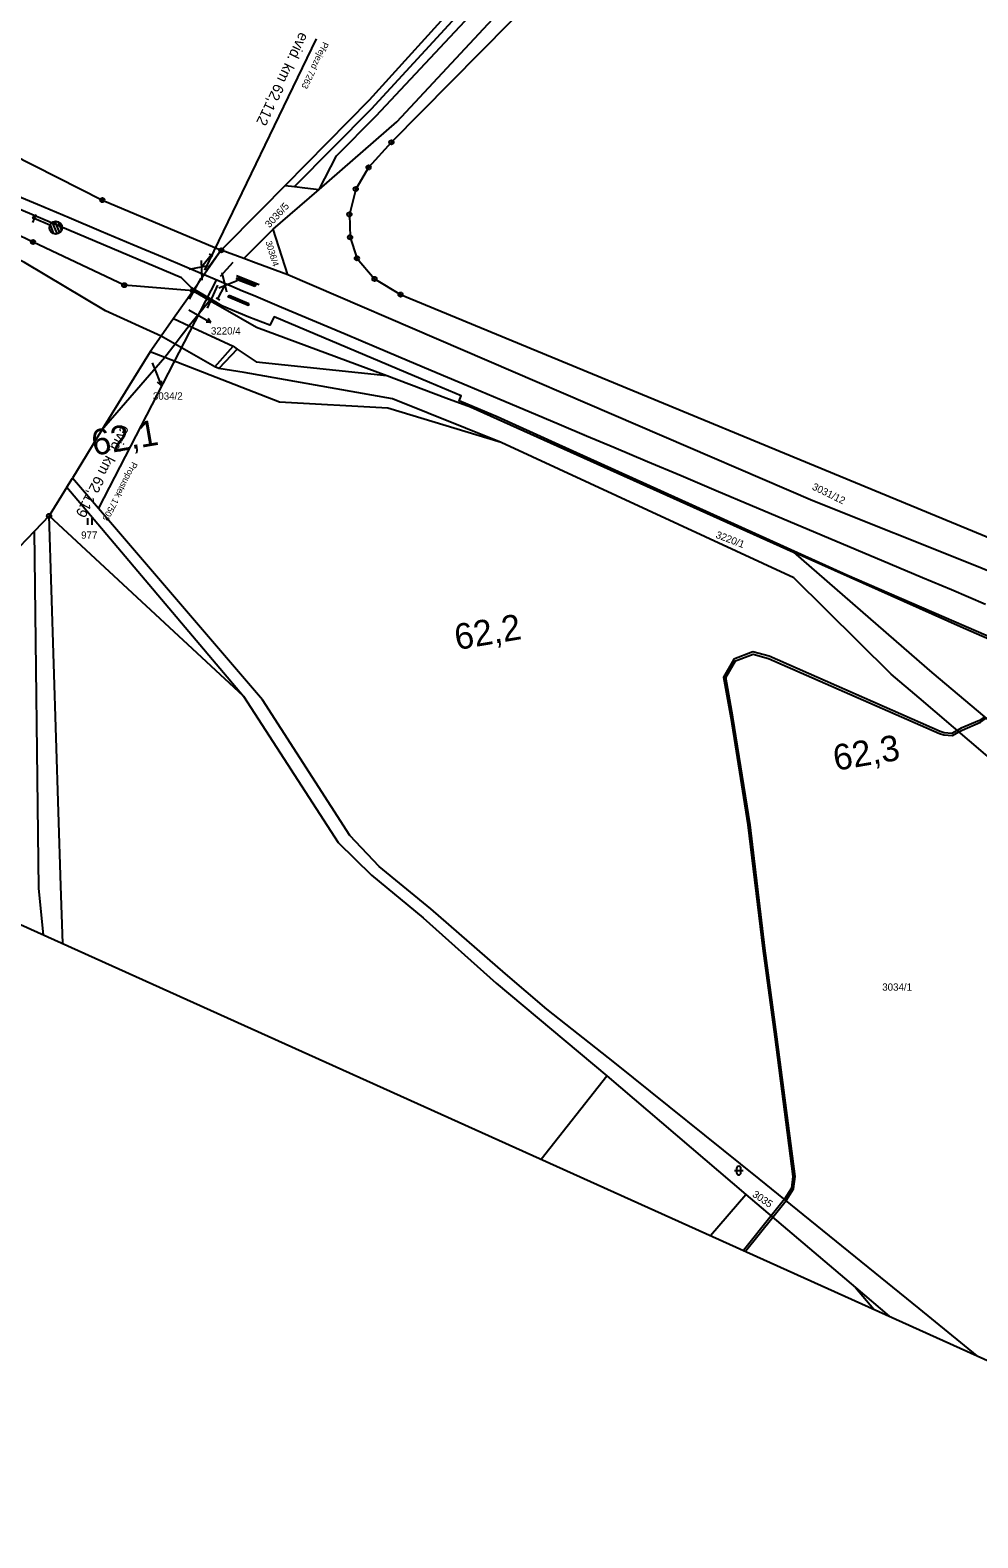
# Model space of a CAD drawing. Extents: x -621716 to -621020, y -1122350 to -1121821.
# Drawn here: x -621457.9 to -621236.3, y -1122350.4 to -1121998 of the extents above; entities that cross this region are included whole.
import ezdxf

# ---------------------------------------------------------------- set-up
doc = ezdxf.new("R2010")
doc.units = 0
for name, color, linetype in [('hm', 7, 'Continuous'), ('HranDP', 7, 'Continuous'), ('Hranice parcel', 7, 'Continuous'), ('Parcelní čísla', 7, 'Continuous'), ('Pop  PČ popisy', 7, 'Continuous'), ('Rámečky-tisk', 7, 'Continuous'), ('STANICENI NOVE HM', 7, 'Continuous'), ('Vnitřní kresba', 7, 'Continuous'), ('Vrstva 1', 7, 'Continuous'), ('Vrstva 18', 7, 'Continuous'), ('Vrstva 19', 7, 'Continuous'), ('Vrstva 2', 7, 'Continuous'), ('Vrstva 4', 7, 'Continuous'), ('Vrstva 51', 7, 'Continuous'), ('Věcná břemena k části', 7, 'Continuous'), ('Značky bodu BP', 7, 'Continuous'), ('Značky kultur', 7, 'Continuous')]:
    doc.layers.add(name, color=color, linetype=linetype)

msp = doc.modelspace()

# ---------------------------------------------------------------- linework, layer by layer
at = {"layer": 'hm'}
for p, q in [((-621420.45, -1122053.43), (-621420.45, -1122053.43)), ((-621328.28, -1122092.36), (-621328.28, -1122092.36))]:
    msp.add_line(p, q, dxfattribs=at)
at = {"layer": 'HranDP'}
for p, q in [((-621407.88, -1122051.37), (-621413.16, -1122049.43)), ((-621419.76, -1122058.87), (-621415.82, -1122061.13)), ((-621240.3, -1122137.45), (-621279.41, -1122120.03))]:
    msp.add_line(p, q, dxfattribs=at)
for points in [[(-621652.52, -1121949.92), (-621634.32, -1121957.84), (-621586.09, -1121979.87), (-621558.65, -1121986.81), (-621503.12, -1122006.48), (-621467.56, -1122024.2), (-621440.98, -1122037.68), (-621413.16, -1122049.43)], [(-621419.76, -1122058.87), (-621435.87, -1122057.58), (-621457.19, -1122047.49), (-621484.84, -1122034.47), (-621524.13, -1122018.29), (-621524.58, -1122018.11), (-621531.16, -1122015.54)], [(-621397.6, -1122055.13), (-621405.03, -1122052.42), (-621407.88, -1122051.37)], [(-621236.6, -1122123.3), (-621274.82, -1122107.97), (-621397.6, -1122055.13)], [(-621415.82, -1122061.13), (-621412.83, -1122062.84), (-621404.9, -1122067.41), (-621374.43, -1122078.72), (-621360.65, -1122083.94), (-621354.93, -1122086.03), (-621279.41, -1122120.03)], [(-621071.57, -1122194.18), (-621089.46, -1122186.34), (-621091.58, -1122185.41), (-621183.06, -1122145.34), (-621236.6, -1122123.3)], [(-621077.02, -1122206.26), (-621096.79, -1122198.16), (-621171.69, -1122167.46), (-621240.3, -1122137.45)]]:
    msp.add_lwpolyline(points, dxfattribs=at)
at = {"layer": 'Hranice parcel'}
for p, q in [((-621338.16, -1121969.67), (-621378.6, -1122014.36)), ((-621338.16, -1121969.67), (-621378.6, -1122014.36)), ((-621378.6, -1122014.36), (-621398.24, -1122034.29)), ((-621378.6, -1122014.36), (-621398.24, -1122034.29)), ((-621390.3, -1122035.18), (-621372.11, -1122019.37)), ((-621398.24, -1122034.29), (-621403.84, -1122039.98)), ((-621398.24, -1122034.29), (-621403.84, -1122039.98)), ((-621398.24, -1122034.29), (-621396.07, -1122034.53)), ((-621403.84, -1122039.98), (-621413.16, -1122049.43)), ((-621403.84, -1122039.98), (-621413.16, -1122049.43)), ((-621401.06, -1122044.51), (-621407.88, -1122051.37)), ((-621397.6, -1122055.13), (-621401.06, -1122044.51)), ((-621413.16, -1122049.43), (-621417.06, -1122055.01)), ((-621413.16, -1122049.43), (-621417.06, -1122055.01)), ((-621407.88, -1122051.37), (-621413.16, -1122049.43)), ((-621417.06, -1122055.01), (-621419.76, -1122058.87)), ((-621417.06, -1122055.01), (-621419.76, -1122058.87)), ((-621419.76, -1122058.87), (-621424.34, -1122065.38)), ((-621419.76, -1122058.87), (-621424.34, -1122065.38)), ((-621419.76, -1122058.87), (-621415.82, -1122061.13)), ((-621424.34, -1122065.38), (-621427.21, -1122069.47)), ((-621424.34, -1122065.38), (-621427.21, -1122069.47)), ((-621427.21, -1122069.47), (-621429.78, -1122073.13)), ((-621427.21, -1122069.47), (-621429.78, -1122073.13)), ((-621423.93, -1122071.34), (-621427.21, -1122069.47)), ((-621414.64, -1122076.64), (-621423.93, -1122071.34)), ((-621441.14, -1122091.59), (-621447.98, -1122102.71)), ((-621441.14, -1122091.59), (-621447.98, -1122102.71)), ((-621449.3, -1122104.83), (-621447.98, -1122102.71)), ((-621449.3, -1122104.83), (-621447.98, -1122102.71)), ((-621449.3, -1122104.83), (-621453.42, -1122111.52)), ((-621449.3, -1122104.83), (-621453.42, -1122111.52)), ((-621449.3, -1122104.83), (-621407.95, -1122153.65)), ((-621449.3, -1122104.83), (-621407.95, -1122153.65)), ((-621453.42, -1122111.52), (-621456.82, -1122115.07)), ((-621453.42, -1122111.52), (-621456.82, -1122115.07)), ((-621407.95, -1122153.65), (-621453.42, -1122111.52)), ((-621456.82, -1122115.07), (-621487.9, -1122147.44)), ((-621456.82, -1122115.07), (-621487.9, -1122147.44)), ((-621240.3, -1122137.45), (-621279.41, -1122120.03)), ((-621407.95, -1122153.65), (-621385.83, -1122187.85)), ((-621407.95, -1122153.65), (-621385.83, -1122187.85)), ((-621348.86, -1122220.77), (-621323.04, -1122242.46)), ((-621348.86, -1122220.77), (-621323.04, -1122242.46)), ((-621323.04, -1122242.46), (-621290.49, -1122270.16)), ((-621323.04, -1122242.46), (-621290.49, -1122270.16)), ((-621290.49, -1122270.16), (-621264.88, -1122291.93)), ((-621290.49, -1122270.16), (-621264.88, -1122291.93)), ((-621264.88, -1122291.93), (-621257.02, -1122298.61)), ((-621264.88, -1122291.93), (-621257.02, -1122298.61))]:
    msp.add_line(p, q, dxfattribs=at)
for points in [[(-621652.52, -1121949.92), (-621634.32, -1121957.84), (-621586.09, -1121979.87), (-621558.65, -1121986.81), (-621503.12, -1122006.48), (-621467.56, -1122024.2), (-621440.98, -1122037.68), (-621413.16, -1122049.43)], [(-621390.3, -1122035.18), (-621386.25, -1122027.37), (-621376.94, -1122017.95), (-621351.6, -1121990.87), (-621337.62, -1121976.15), (-621310.12, -1121948.89)], [(-621316.28, -1121963.73), (-621318.05, -1121968.15), (-621373.38, -1122024.18), (-621378.72, -1122030.05), (-621381.72, -1122035.12), (-621383.2, -1122041.04), (-621383.06, -1122046.37), (-621381.45, -1122051.28), (-621377.34, -1122056.11), (-621371.25, -1122059.79), (-621220, -1122122.28), (-621154.89, -1122148.82), (-621067.38, -1122184.88)], [(-621396.07, -1122034.53), (-621378.06, -1122016.33), (-621337.5, -1121972.28)], [(-621372.11, -1122019.37), (-621337.97, -1121982.66), (-621329.83, -1121972.98)], [(-621419.76, -1122058.87), (-621435.87, -1122057.58), (-621457.19, -1122047.49), (-621484.84, -1122034.47), (-621524.13, -1122018.29), (-621524.58, -1122018.11), (-621531.16, -1122015.54)], [(-621427.21, -1122069.47), (-621440.23, -1122063.56), (-621459.21, -1122052.3), (-621481.49, -1122041.55), (-621489.69, -1122037.91), (-621514.45, -1122027.88), (-621531.58, -1122025.1), (-621539.57, -1122026.3)], [(-621401.06, -1122044.51), (-621397.09, -1122041.07), (-621390.3, -1122035.18)], [(-621396.07, -1122034.53), (-621393.61, -1122034.81), (-621390.3, -1122035.18)], [(-621397.6, -1122055.13), (-621405.03, -1122052.42), (-621407.88, -1122051.37)], [(-621236.6, -1122123.3), (-621274.82, -1122107.97), (-621397.6, -1122055.13)], [(-621415.82, -1122061.13), (-621420.66, -1122067.08), (-621422.55, -1122069.54), (-621423.93, -1122071.34)], [(-621415.82, -1122061.13), (-621412.83, -1122062.84), (-621404.9, -1122067.41), (-621374.43, -1122078.72), (-621360.65, -1122083.94), (-621354.93, -1122086.03), (-621279.41, -1122120.03)], [(-621423.93, -1122071.34), (-621426.34, -1122074.48), (-621441.14, -1122091.59)], [(-621429.78, -1122073.13), (-621435, -1122081.61), (-621441.14, -1122091.59)], [(-621429.78, -1122073.13), (-621435, -1122081.61), (-621441.14, -1122091.59)], [(-621187.4, -1122207.5), (-621250, -1122154.05), (-621256.5, -1122148.5), (-621279.33, -1122126.02), (-621347.74, -1122094.36), (-621373.17, -1122084.12), (-621407.84, -1122078), (-621413.72, -1122077.04), (-621414.64, -1122076.64)], [(-621236.42, -1122307.9), (-621250, -1122296.86), (-621287.36, -1122266.52), (-621321.13, -1122239.4), (-621337.07, -1122226.87), (-621346.7, -1122218.55), (-621364.2, -1122203.4), (-621376.27, -1122193.53), (-621383.11, -1122186.25), (-621403.55, -1122154.5), (-621447.98, -1122102.71)], [(-621450.22, -1122211.51), (-621450.7, -1122198.05), (-621453.42, -1122111.52)], [(-621454.75, -1122209.47), (-621455.81, -1122198.63), (-621456.82, -1122115.07)], [(-621279.41, -1122120.03), (-621250, -1122145.55), (-621247, -1122148.15)], [(-621071.57, -1122194.18), (-621089.46, -1122186.34), (-621091.58, -1122185.41), (-621183.06, -1122145.34), (-621236.6, -1122123.3)], [(-621077.02, -1122206.26), (-621096.79, -1122198.16), (-621171.69, -1122167.46), (-621240.3, -1122137.45)], [(-621247, -1122148.15), (-621183.91, -1122201.29), (-621138.49, -1122229.74), (-621120.6, -1122238.74), (-621097.01, -1122250.61)], [(-621385.83, -1122187.85), (-621378.02, -1122195.51), (-621365.96, -1122205.51), (-621348.86, -1122220.77)], [(-621385.83, -1122187.85), (-621378.02, -1122195.51), (-621365.96, -1122205.51), (-621348.86, -1122220.77)], [(-621338.34, -1122261.95), (-621323.04, -1122242.46)], [(-621298.77, -1122279.79), (-621290.49, -1122270.16)], [(-621264.88, -1122291.93), (-621260.6, -1122296.99)]]:
    msp.add_lwpolyline(points, dxfattribs=at)
at = {"layer": 'Pop  PČ popisy'}
for p, q in [((-621420.74, -1122063.35), (-621418.19, -1122064.8)), ((-621418.19, -1122064.8), (-621415.59, -1122066.3)), ((-621415.59, -1122066.3), (-621416.71, -1122066.23)), ((-621415.59, -1122066.3), (-621416.21, -1122065.37)), ((-621429.33, -1122075.75), (-621428.34, -1122078.24)), ((-621428.34, -1122078.24), (-621427.22, -1122081.02)), ((-621427.22, -1122081.02), (-621428.06, -1122080.28)), ((-621427.22, -1122081.02), (-621427.13, -1122079.91))]:
    msp.add_line(p, q, dxfattribs=at)
at = {"layer": 'Rámečky-tisk'}
msp.add_lwpolyline([(-621594.3, -1121820.78), (-621716.36, -1122091.54), (-621142.02, -1122350.45)], dxfattribs=at)
at = {"layer": 'Vnitřní kresba'}
for p, q in [((-621409.58, -1122056.22), (-621409.4, -1122055.76)), ((-621405.31, -1122057.91), (-621409.58, -1122056.22)), ((-621409.4, -1122055.76), (-621405.12, -1122057.45)), ((-621411.51, -1122060.4), (-621411.33, -1122059.94)), ((-621406.92, -1122062.32), (-621411.51, -1122060.4)), ((-621411.33, -1122059.94), (-621406.73, -1122061.86)), ((-621405.12, -1122057.45), (-621405.31, -1122057.91)), ((-621406.73, -1122061.86), (-621406.92, -1122062.32)), ((-621424.34, -1122065.38), (-621420.66, -1122067.08)), ((-621420.66, -1122067.08), (-621410.38, -1122071.81)), ((-621426.34, -1122074.48), (-621429.78, -1122073.13)), ((-621399.58, -1122084.94), (-621426.34, -1122074.48)), ((-621414.64, -1122076.64), (-621410.38, -1122071.81)), ((-621409.44, -1122072.55), (-621413.72, -1122077.04)), ((-621410.38, -1122071.81), (-621409.44, -1122072.55)), ((-621409.44, -1122072.55), (-621405.01, -1122075.53)), ((-621405.01, -1122075.53), (-621374.43, -1122078.72)), ((-621374.22, -1122086.34), (-621399.58, -1122084.94)), ((-621347.74, -1122094.36), (-621374.22, -1122086.34))]:
    msp.add_line(p, q, dxfattribs=at)
at = {"layer": 'Vrstva 1'}
for p, q in [((-621456.94, -1122041.27), (-621465.24, -1122037.77)), ((-621414.87, -1122061.31), (-621420.14, -1122058.23)), ((-621413.03, -1122062.38), (-621414.87, -1122061.31)), ((-621406.73, -1122065.04), (-621413.03, -1122062.38))]:
    msp.add_line(p, q, dxfattribs=at)
for points in [[(-621463.6, -1122035.5), (-621456.14, -1122038.65), (-621448.71, -1122041.78), (-621441.28, -1122044.92), (-621433.82, -1122048.06), (-621426.01, -1122051.35), (-621418.67, -1122054.45), (-621413.13, -1122056.78), (-621410.7, -1122057.8), (-621408.17, -1122058.87), (-621405.64, -1122059.94), (-621399.12, -1122062.69), (-621391.8, -1122065.77), (-621384.21, -1122068.97), (-621376.84, -1122072.09), (-621369.7, -1122075.09), (-621362.7, -1122078.04), (-621355.46, -1122081.1), (-621348.02, -1122084.24), (-621341.21, -1122087.11), (-621334.15, -1122090.09), (-621327.75, -1122092.8), (-621321.37, -1122095.49), (-621313.5, -1122098.8), (-621305.66, -1122102.11), (-621297.43, -1122105.59), (-621288.95, -1122109.16), (-621280.64, -1122112.66), (-621272.65, -1122116.04), (-621264.7, -1122119.38), (-621256.74, -1122122.74), (-621249.24, -1122125.9), (-621242.46, -1122128.76), (-621234.48, -1122132.13)], [(-621456.93, -1122042.01), (-621457.21, -1122041.89), (-621456.94, -1122041.27)], [(-621420.14, -1122058.23), (-621422.44, -1122055.84), (-621456.94, -1122041.27)], [(-621085.52, -1122202.49), (-621145.97, -1122177.73), (-621266.9, -1122125.34), (-621335.07, -1122094.53), (-621348.64, -1122088.4), (-621357.58, -1122084.62), (-621357.08, -1122083.45), (-621364.5, -1122080.32), (-621400.77, -1122065), (-621401.81, -1122066.92), (-621406.73, -1122065.04)]]:
    msp.add_lwpolyline(points, dxfattribs=at)
at = {"layer": 'Vrstva 18'}
for p, q in [((-621404.34, -1122057.53), (-621409.61, -1122055.39)), ((-621406.64, -1122062.36), (-621411.73, -1122060.23))]:
    msp.add_line(p, q, dxfattribs=at)
at = {"layer": 'Vrstva 19'}
msp.add_line((-621441.76, -1122109.75), (-621414.31, -1122056.4), dxfattribs=at)
at = {"layer": 'Vrstva 2'}
for p, q in [((-621456.54, -1122041.09), (-621457.32, -1122042.93)), ((-621453.25, -1122043.57), (-621456.93, -1122042.01)), ((-621452.68, -1122042.89), (-621451.57, -1122045.62)), ((-621452.05, -1122042.66), (-621450.99, -1122045.37)), ((-621451.37, -1122042.73), (-621450.52, -1122044.82)), ((-621453.21, -1122043.48), (-621452.36, -1122045.57))]:
    msp.add_line(p, q, dxfattribs=at)
msp.add_circle((-621451.86, -1122044.15), 1.5, dxfattribs=at)
at = {"layer": 'Vrstva 4'}
for p, q in [((-621417.03, -1122054.04), (-621390.9, -1122000.02)), ((-621416.24, -1122053.04), (-621420.78, -1122053.89)), ((-621417.66, -1122056.39), (-621417.8, -1122051.78)), ((-621415.55, -1122050.58), (-621417.74, -1122053.31)), ((-621415.16, -1122050.89), (-621415.94, -1122050.26)), ((-621418.67, -1122054.45), (-621413.13, -1122056.78)), ((-621413.76, -1122058.2), (-621409.49, -1122056.47)), ((-621413.04, -1122054.64), (-621411.98, -1122059.12)), ((-621414.4, -1122060.52), (-621413.51, -1122060.98)), ((-621413.95, -1122060.75), (-621412.34, -1122057.64))]:
    msp.add_line(p, q, dxfattribs=at)
at = {"layer": 'Vrstva 51'}
for p, q in [((-621413.66, -1122050.02), (-621416.66, -1122054.16)), ((-621410.46, -1122052.3), (-621413.39, -1122055.56)), ((-621420.6, -1122060.83), (-621417.9, -1122055.93)), ((-621416.39, -1122062.99), (-621413.99, -1122057.55))]:
    msp.add_line(p, q, dxfattribs=at)
at = {"layer": 'Věcná břemena k části'}
msp.add_line((-621291.09, -1122283.25), (-621290.63, -1122283.46), dxfattribs=at)
for points in [[(-621242.32, -1122162.36), (-621244.11, -1122162.22), (-621245.08, -1122161.9), (-621285.04, -1122144.35), (-621288.86, -1122143.32), (-621293.29, -1122145), (-621295.74, -1122149.19), (-621294.06, -1122158.66), (-621290.04, -1122183.78), (-621286.56, -1122212.67), (-621283.77, -1122233.35), (-621279.5, -1122265.97), (-621279.82, -1122268.68), (-621281.5, -1122271.28), (-621281.11, -1122271.59), (-621281.1, -1122271.58), (-621279.34, -1122268.86), (-621279, -1122265.97), (-621283.27, -1122233.29), (-621286.06, -1122212.61), (-621289.54, -1122183.72), (-621293.56, -1122158.58), (-621295.22, -1122149.29), (-621292.95, -1122145.4), (-621288.84, -1122143.84), (-621285.2, -1122144.83), (-621245.26, -1122162.36), (-621244.21, -1122162.72), (-621242.2, -1122162.86), (-621240.68, -1122162.01), (-621241.08, -1122161.66)], [(-621234.35, -1122158.81), (-621234.74, -1122158.48), (-621235.87, -1122159.33), (-621240.17, -1122161.16), (-621241.08, -1122161.66), (-621240.68, -1122162.01), (-621239.95, -1122161.6), (-621235.61, -1122159.77)], [(-621281.11, -1122271.59), (-621281.5, -1122271.28), (-621284.61, -1122275.16), (-621284.23, -1122275.48)]]:
    msp.add_lwpolyline(points, close=True, dxfattribs=at)
msp.add_lwpolyline([(-621290.63, -1122283.46), (-621284.23, -1122275.48), (-621284.61, -1122275.16), (-621291.09, -1122283.25)], dxfattribs=at)
at = {"layer": 'Značky bodu BP'}
for centre, radius in [((-621373.38, -1122024.18), 0.5), ((-621373.38, -1122024.18), 0.0303), ((-621378.72, -1122030.05), 0.5), ((-621378.72, -1122030.05), 0.0303), ((-621381.72, -1122035.12), 0.5), ((-621381.72, -1122035.12), 0.0303), ((-621440.98, -1122037.68), 0.5), ((-621440.98, -1122037.68), 0.0303), ((-621383.2, -1122041.04), 0.5), ((-621383.2, -1122041.04), 0.0303), ((-621383.06, -1122046.37), 0.5), ((-621383.06, -1122046.37), 0.0303), ((-621457.19, -1122047.49), 0.5), ((-621457.19, -1122047.49), 0.0303), ((-621413.16, -1122049.43), 0.5), ((-621413.16, -1122049.43), 0.0303), ((-621381.45, -1122051.28), 0.5), ((-621381.45, -1122051.28), 0.0303), ((-621435.87, -1122057.58), 0.5), ((-621377.34, -1122056.11), 0.5), ((-621377.34, -1122056.11), 0.0303), ((-621435.87, -1122057.58), 0.0303), ((-621419.76, -1122058.87), 0.5), ((-621419.76, -1122058.87), 0.0303), ((-621371.25, -1122059.79), 0.5), ((-621371.25, -1122059.79), 0.0303), ((-621453.42, -1122111.52), 0.5), ((-621453.42, -1122111.52), 0.0303)]:
    msp.add_circle(centre, radius, dxfattribs=at)
at = {"layer": 'Značky kultur'}
for p, q in [((-621444.37, -1122113.59), (-621444.37, -1122112.09)), ((-621443.37, -1122113.59), (-621443.37, -1122112.09)), ((-621293.17, -1122264.59), (-621291.17, -1122264.59)), ((-621292.67, -1122264.09), (-621292.67, -1122265.09)), ((-621291.67, -1122265.09), (-621291.67, -1122264.09))]:
    msp.add_line(p, q, dxfattribs=at)
for centre, start, end in [((-621292.17, -1122264.09), 0, 180), ((-621292.17, -1122265.09), 180, 359.9879)]:
    msp.add_arc(centre, 0.5, start, end, dxfattribs=at)

# ---------------------------------------------------------------- texts
at = {"layer": 'Parcelní čísla'}
for s, height, rotation, p in [('3036/5', 1.7, 47, (-621401.9, -1122044.31)), ('3036/4', 1.5, 287, (-621402.85, -1122047.46)), ('3031/12', 1.7, 334, (-621275.18, -1122105.26)), ('3220/1', 1.7, 339, (-621297.7, -1122116.58)), ('3035', 1.7, 326, (-621289.15, -1122270.52))]:
    msp.add_text(s, height=height, rotation=rotation, dxfattribs=at).set_placement(p)
for s, p in [('3220/4', (-621415.59, -1122069.12)), ('3034/2', (-621429.15, -1122084.35)), ('977', (-621445.93, -1122116.86)), ('3034/1', (-621258.62, -1122222.53))]:
    msp.add_text(s, height=1.7, dxfattribs=at).set_placement(p)
at = {"layer": 'STANICENI NOVE HM'}
for s, p in [('62,1', (-621442.96, -1122097.48)), ('62,2', (-621358.1, -1122142.91)), ('62,3', (-621269.56, -1122171.14))]:
    msp.add_text(s, height=6, rotation=9.6991, dxfattribs=at).set_placement(p)
at = {"layer": 'Vrstva 19'}
for s, height, p in [('evid. km 62,119', 2.5, (-621436.41, -1122090.12)), ('Propustek 17503', 1.5, (-621433.98, -1122098.76))]:
    msp.add_text(s, height=height, rotation=242.5095, dxfattribs=at).set_placement(p)
at = {"layer": 'Vrstva 4'}
for s, height, p in [('evid. km 62,112', 2.5, (-621394.79, -1121998.25)), ('Přejezd 7263', 1.5, (-621389.33, -1122000.56))]:
    msp.add_text(s, height=height, rotation=244.1905, dxfattribs=at).set_placement(p)

doc.saveas('drawing.dxf')
